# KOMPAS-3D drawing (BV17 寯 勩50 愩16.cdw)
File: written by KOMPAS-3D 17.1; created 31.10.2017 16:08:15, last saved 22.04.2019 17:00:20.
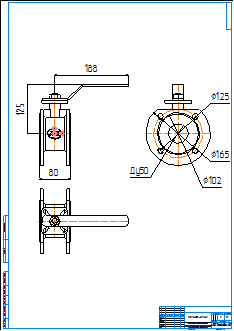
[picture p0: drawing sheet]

Sheet 1: A1, portrait

Title block, sheet 1: name: BV17 МФ Ду50 Ру16; material: Внимание! Данный продукт является объектом авторского права ООО «Торговый Дом АДЛ». / Запрещается изменение, копирование, распространение / (в том числе путем копирования на другие сайты и ресурсы в Интернете) / или любое иное использование информации и объектов без предварительного / согласия правообладателя (ООО «Торговый Дом АДЛ»).; mass: 1; sheets: 1; organisation: ООО "Торговый дом АДЛ"; sheet format: A1; stored path: \\adlc.lan\data\АДЛ_ПКД\3D-модели\ADL production\Краны шаровые серии BV\BV17 МФ Нержавеющие Ру16\KOMPAS 2D\BV17 МФ Ду50 Ру16.cdw

Views: Вид 1, Проекционный вид 2, Проекционный вид 3
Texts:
  kka
  adl
Dimensions and other numbers on the sheet: 80; 188; 125; 50; 165; 102; 1:1; 1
